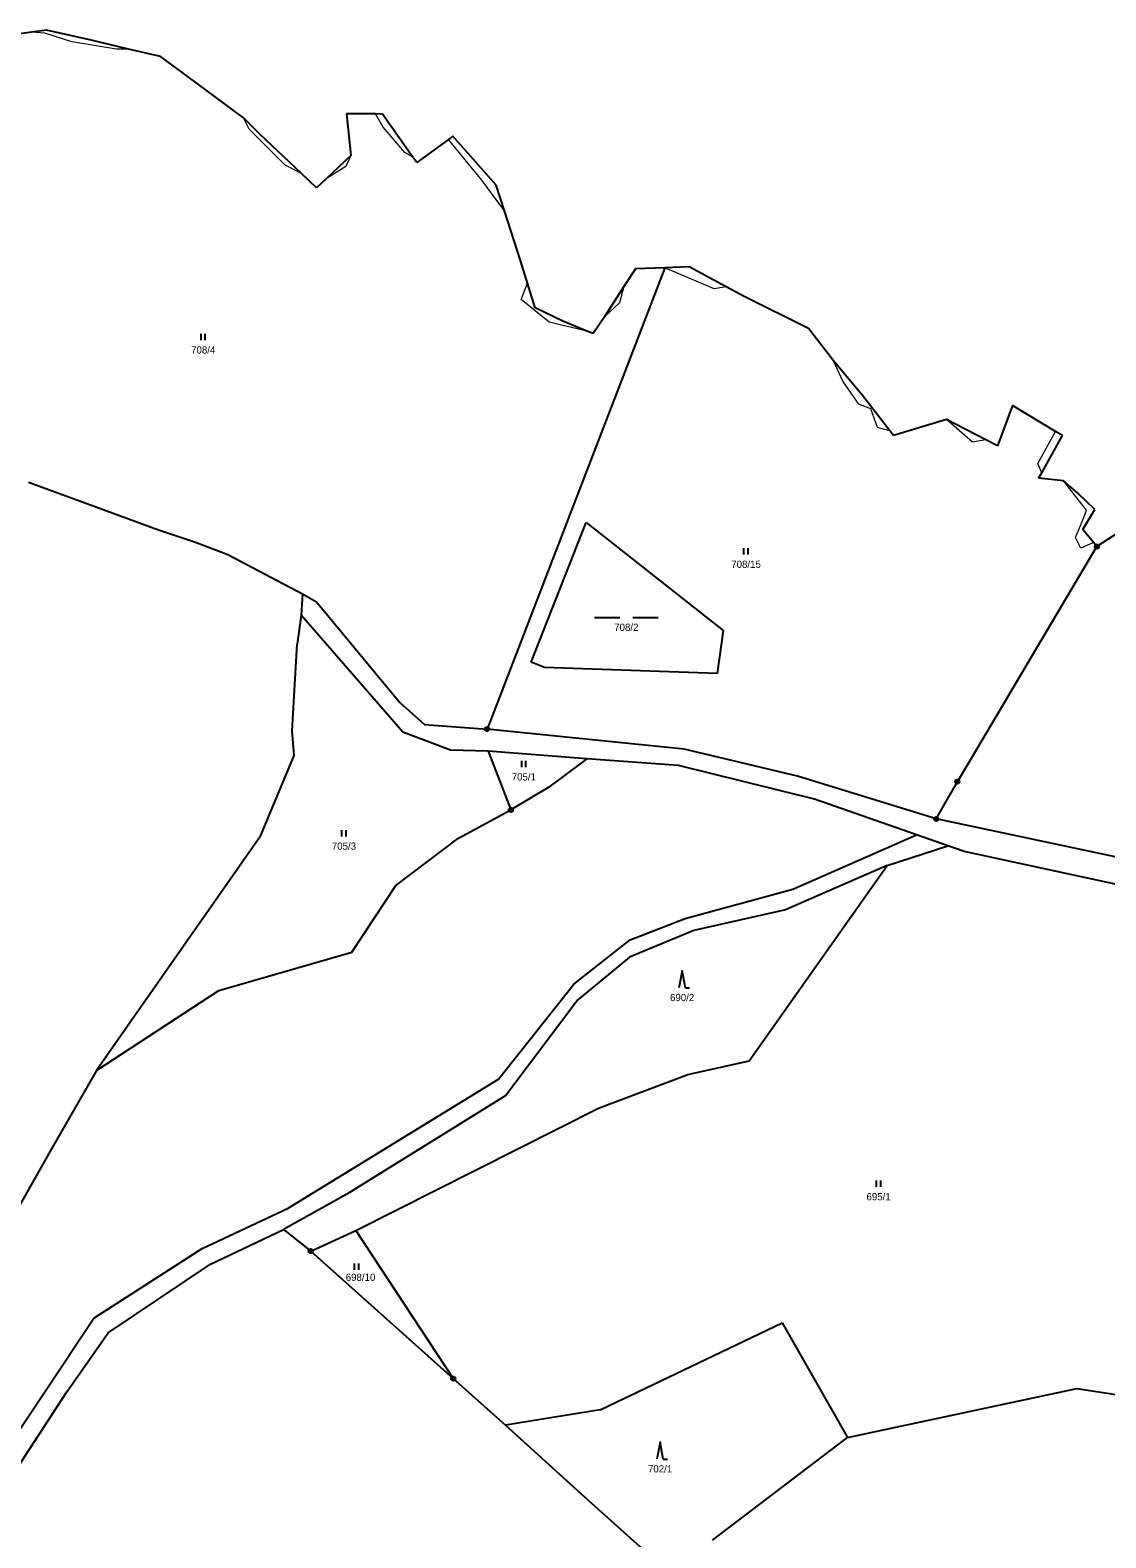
# Model space of a CAD drawing. Extents: x -739410 to -735662, y -942282 to -940043.
# Drawn here: x -738926.3 to -738673.5, y -941488.5 to -941134.3 of the extents above; entities that cross this region are included whole.
import ezdxf
from ezdxf.enums import TextEntityAlignment as Align

# ---------------------------------------------------------------- set-up
doc = ezdxf.new("R2010")
doc.units = 0
doc.header["$LTSCALE"] = 0.68
for name, color, linetype, lineweight in [('1', 7, 'Continuous', 25), ('3', 7, 'Continuous', 25), ('4', 7, 'Continuous', 13), ('8', 7, 'Continuous', 25)]:
    doc.layers.add(name, color=color, linetype=linetype, lineweight=lineweight)
doc.layers.add('2', color=7, linetype='Continuous')

msp = doc.modelspace()

# ---------------------------------------------------------------- linework, layer by layer
at = {"layer": '1'}
for p, q in [((-738925.92, -941134.78), (-738932.51, -941135.73)), ((-738922.47, -941134.29), (-738925.92, -941134.78)), ((-738911.93, -941136.68), (-738922.47, -941134.29)), ((-738903.14, -941138.74), (-738911.93, -941136.68)), ((-738895.68, -941140.49), (-738903.14, -941138.74)), ((-738889.13, -941145.22), (-738895.68, -941140.49)), ((-738876.12, -941154.87), (-738889.13, -941145.22)), ((-738872.28, -941158.73), (-738876.12, -941154.87)), ((-738851.94, -941153.93), (-738850.94, -941163.74)), ((-738845.13, -941153.98), (-738851.94, -941153.93)), ((-738843.49, -941153.99), (-738845.13, -941153.98)), ((-738836.41, -941164.03), (-738843.49, -941153.99)), ((-738862.51, -941168), (-738872.28, -941158.73)), ((-738826.94, -941159.23), (-738827.96, -941159.97)), ((-738816.76, -941170.68), (-738826.94, -941159.23)), ((-738827.96, -941159.97), (-738835.45, -941165.4)), ((-738850.94, -941163.74), (-738856.71, -941169.19)), ((-738835.45, -941165.4), (-738836.41, -941164.03)), ((-738858.99, -941171.34), (-738862.51, -941168)), ((-738856.71, -941169.19), (-738858.99, -941171.34)), ((-738814.81, -941176.75), (-738816.76, -941170.68)), ((-738811.06, -941188.39), (-738814.81, -941176.75)), ((-738777.17, -941190.11), (-738818.9, -941298.52)), ((-738809.41, -941193.73), (-738811.06, -941188.39)), ((-738784.06, -941190.39), (-738786.75, -941194.55)), ((-738777.17, -941190.11), (-738784.06, -941190.39)), ((-738771.44, -941189.89), (-738777.17, -941190.11)), ((-738762.72, -941194.6), (-738771.44, -941189.89)), ((-738807.6, -941199.56), (-738809.41, -941193.73)), ((-738786.75, -941194.55), (-738791.36, -941201.67)), ((-738758.51, -941196.87), (-738762.72, -941194.6)), ((-738743.38, -941204.38), (-738758.51, -941196.87)), ((-738801.11, -941202.63), (-738807.6, -941199.56)), ((-738791.36, -941201.67), (-738794.01, -941205.58)), ((-738795.46, -941204.98), (-738801.11, -941202.63)), ((-738794.01, -941205.58), (-738795.46, -941204.98)), ((-738724.25, -941228.42), (-738730.7, -941220.09)), ((-738695.48, -941222.44), (-738698.99, -941231.96)), ((-738685.36, -941228.57), (-738695.48, -941222.44)), ((-738710.94, -941225.77), (-738723.41, -941229.51)), ((-738701.71, -941230.55), (-738710.94, -941225.77)), ((-738723.41, -941229.51), (-738724.25, -941228.42)), ((-738698.99, -941231.96), (-738701.71, -941230.55)), ((-738688.61, -941238.29), (-738683.73, -941229.56)), ((-738683.73, -941229.56), (-738685.36, -941228.57)), ((-738926.63, -941240.49), (-738910.57, -941246.37)), ((-738689.32, -941239.56), (-738688.61, -941238.29)), ((-738683.49, -941240.16), (-738689.32, -941239.56)), ((-738680.13, -941243.05), (-738683.49, -941240.16)), ((-738676.09, -941246.88), (-738680.13, -941243.05)), ((-738910.57, -941246.37), (-738896.15, -941251.67)), ((-738678.98, -941251.65), (-738676.09, -941246.88)), ((-738896.15, -941251.67), (-738887.44, -941254.55)), ((-738808.55, -941282.75), (-738795.6, -941249.99)), ((-738795.6, -941249.99), (-738763.42, -941275.38)), ((-738676.44, -941254.66), (-738678.98, -941251.65)), ((-738665.06, -941248.73), (-738675.63, -941255.63)), ((-738887.44, -941254.55), (-738879.84, -941257.52)), ((-738675.63, -941255.63), (-738676.44, -941254.66)), ((-738879.84, -941257.52), (-738862.29, -941266.76)), ((-738708.42, -941310.86), (-738675.63, -941255.63)), ((-738862.29, -941266.76), (-738862.62, -941271.76)), ((-738862.29, -941266.76), (-738859, -941268.57)), ((-738859, -941268.57), (-738839.4, -941292.25)), ((-738862.62, -941271.76), (-738863.56, -941278.52)), ((-738838.71, -941299.26), (-738862.62, -941271.76)), ((-738763.42, -941275.38), (-738764.85, -941285.48)), ((-738864.75, -941298.95), (-738863.56, -941278.52)), ((-738805.39, -941284), (-738808.55, -941282.75)), ((-738764.85, -941285.48), (-738805.39, -941284)), ((-738839.4, -941292.25), (-738833.6, -941297.42)), ((-738833.6, -941297.42), (-738818.9, -941298.52)), ((-738864.26, -941304.72), (-738864.75, -941298.95)), ((-738827.49, -941303.43), (-738838.71, -941299.26)), ((-738772.6, -941303.2), (-738818.9, -941298.52)), ((-738872.13, -941323.67), (-738864.26, -941304.72)), ((-738818.68, -941303.66), (-738827.49, -941303.43)), ((-738818.68, -941303.66), (-738813.33, -941317.49)), ((-738795.51, -941305.47), (-738818.68, -941303.66)), ((-738745.97, -941309.54), (-738772.6, -941303.2)), ((-738795.51, -941305.47), (-738804.44, -941312.19)), ((-738773.94, -941307.05), (-738795.51, -941305.47)), ((-738741.99, -941314.94), (-738773.94, -941307.05)), ((-738804.44, -941312.19), (-738813.33, -941317.49)), ((-738713.4, -941319.63), (-738745.97, -941309.54)), ((-738713.4, -941319.63), (-738708.42, -941310.86)), ((-738718.04, -941323.34), (-738741.99, -941314.94)), ((-738825.6, -941324.14), (-738813.33, -941317.49)), ((-738668.73, -941329.06), (-738713.4, -941319.63)), ((-738872.13, -941323.67), (-738910.7, -941378.73)), ((-738840.34, -941335.26), (-738825.6, -941324.14)), ((-738747.11, -941336.1), (-738718.04, -941323.34)), ((-738724.92, -941330.59), (-738710.68, -941325.92)), ((-738710.68, -941325.92), (-738718.04, -941323.34)), ((-738706.8, -941327.28), (-738710.68, -941325.92)), ((-738669.84, -941335.26), (-738706.8, -941327.28)), ((-738757.36, -941376.45), (-738724.92, -941330.59)), ((-738724.92, -941330.59), (-738748.77, -941340.98)), ((-738850.68, -941350.9), (-738840.34, -941335.26)), ((-738772.36, -941343.03), (-738747.11, -941336.1)), ((-738785.31, -941348.03), (-738772.36, -941343.03)), ((-738748.77, -941340.98), (-738770.31, -941345.85)), ((-738770.31, -941345.85), (-738785.44, -941352.13)), ((-738881.95, -941359.95), (-738850.68, -941350.9)), ((-738798.52, -941358.42), (-738785.31, -941348.03)), ((-738785.44, -941352.13), (-738797.62, -941362.14)), ((-738910.7, -941378.73), (-738881.95, -941359.95)), ((-738816.21, -941380.73), (-738798.52, -941358.42)), ((-738797.62, -941362.14), (-738814.55, -941384.58)), ((-738910.7, -941378.73), (-738921.59, -941397.65)), ((-738771.72, -941379.66), (-738757.36, -941376.45)), ((-738865.62, -941411.03), (-738816.21, -941380.73)), ((-738792.71, -941387.61), (-738771.72, -941379.66)), ((-738814.55, -941384.58), (-738851.86, -941407.8)), ((-738849.77, -941416.34), (-738792.71, -941387.61)), ((-738921.59, -941397.65), (-738930.47, -941413.51)), ((-738851.86, -941407.8), (-738866.75, -941416.1)), ((-738885.88, -941420.52), (-738865.62, -941411.03)), ((-738883.87, -941424.26), (-738866.75, -941416.1)), ((-738866.75, -941416.1), (-738860.36, -941421.14)), ((-738860.36, -941421.14), (-738849.77, -941416.34)), ((-738849.77, -941416.34), (-738826.86, -941451.12)), ((-738911.35, -941436.94), (-738885.88, -941420.52)), ((-738860.36, -941421.14), (-738826.86, -941451.12)), ((-738907.92, -941440.32), (-738883.87, -941424.26)), ((-738942.74, -941483.93), (-738911.35, -941436.94)), ((-738792.34, -941458.43), (-738749.6, -941437.98)), ((-738749.6, -941437.98), (-738734.21, -941464.91)), ((-738917.62, -941454.18), (-738907.92, -941440.32)), ((-738826.86, -941451.12), (-738814.62, -941462.07)), ((-738734.21, -941464.91), (-738680.39, -941453.41)), ((-738680.39, -941453.41), (-738661.81, -941456.28)), ((-738928.6, -941471.03), (-738917.62, -941454.18)), ((-738792.34, -941458.43), (-738814.62, -941462.07)), ((-738814.62, -941462.07), (-738795.06, -941479.78)), ((-738765.92, -941489.07), (-738734.21, -941464.91)), ((-738795.06, -941479.78), (-738772.58, -941499.84))]:
    msp.add_line(p, q, dxfattribs=at)
msp.add_lwpolyline([(-738730.7, -941220.09), (-738737.52, -941211.97), (-738743.38, -941204.38)], dxfattribs=at)
at = {"layer": '3'}
for p, q in [((-738886.121, -941207.15), (-738886.121, -941205.65)), ((-738885.12, -941207.15), (-738885.12, -941205.65)), ((-738758.581, -941257.5), (-738758.581, -941256)), ((-738757.58, -941257.5), (-738757.58, -941256)), ((-738793.689, -941272.3), (-738787.689, -941272.3)), ((-738784.689, -941272.3), (-738778.689, -941272.3)), ((-738810.791, -941307.46), (-738810.791, -941305.96)), ((-738809.79, -941307.46), (-738809.79, -941305.96)), ((-738853.061, -941323.73), (-738853.061, -941322.23)), ((-738852.06, -941323.73), (-738852.06, -941322.23)), ((-738772.33, -941359.3), (-738771.334, -941359.3)), ((-738727.431, -941406.09), (-738727.431, -941404.59)), ((-738726.43, -941406.09), (-738726.43, -941404.59)), ((-738850.051, -941425.53), (-738850.051, -941424.03)), ((-738849.05, -941425.53), (-738849.05, -941424.03)), ((-738777.52, -941470.04), (-738776.524, -941470.04))]:
    msp.add_line(p, q, dxfattribs=at)
for points in [[(-738772.33, -941359.3), (-738773.08, -941355.3), (-738773.83, -941359.3)], [(-738777.52, -941470.04), (-738778.27, -941466.04), (-738779.02, -941470.04)]]:
    msp.add_lwpolyline(points, dxfattribs=at)
at = {"layer": '4'}
for p, q in [((-738922.8, -941135), (-738925.92, -941134.78)), ((-738916.47, -941137.02), (-738922.8, -941135)), ((-738905.98, -941138.77), (-738916.47, -941137.02)), ((-738903.14, -941138.74), (-738905.98, -941138.77)), ((-738874.83, -941157.55), (-738876.12, -941154.87)), ((-738843.31, -941157.06), (-738845.13, -941153.98)), ((-738866.39, -941166), (-738874.83, -941157.55)), ((-738838.22, -941163.06), (-738843.31, -941157.06)), ((-738836.41, -941164.03), (-738838.22, -941163.06)), ((-738820.18, -941169.51), (-738827.96, -941159.97)), ((-738862.51, -941168), (-738866.39, -941166)), ((-738852.14, -941166.3), (-738856.71, -941169.19)), ((-738850.94, -941163.74), (-738852.14, -941166.3)), ((-738814.81, -941176.75), (-738820.18, -941169.51)), ((-738765.55, -941195.09), (-738777.17, -941190.11)), ((-738810.9, -941197.6), (-738809.41, -941193.73)), ((-738786.75, -941194.55), (-738787.79, -941198.36)), ((-738762.72, -941194.6), (-738765.55, -941195.09)), ((-738804.36, -941202.88), (-738810.9, -941197.6)), ((-738787.79, -941198.36), (-738791.36, -941201.67)), ((-738795.46, -941204.98), (-738804.36, -941202.88)), ((-738735.3, -941216.73), (-738737.52, -941211.97)), ((-738731.58, -941222.19), (-738735.3, -941216.73)), ((-738728.79, -941223.25), (-738731.58, -941222.19)), ((-738727.19, -941227.64), (-738728.79, -941223.25)), ((-738704.86, -941231.09), (-738710.94, -941225.77)), ((-738724.25, -941228.42), (-738727.19, -941227.64)), ((-738701.71, -941230.55), (-738704.86, -941231.09)), ((-738689.51, -941236.09), (-738685.36, -941228.57)), ((-738688.61, -941238.29), (-738689.51, -941236.09)), ((-738678.07, -941247.06), (-738683.49, -941240.16)), ((-738678.74, -941248.79), (-738678.07, -941247.06)), ((-738680.67, -941253.51), (-738678.74, -941248.79)), ((-738679.4, -941255.97), (-738680.67, -941253.51)), ((-738676.44, -941254.66), (-738679.4, -941255.97))]:
    msp.add_line(p, q, dxfattribs=at)
at = {"layer": '8'}
for centre, radius in [((-738675.63, -941255.6299), 0.5), ((-738675.63, -941255.6299), 0.0303), ((-738818.9, -941298.5199), 0.5), ((-738818.9, -941298.5199), 0.0303), ((-738708.42, -941310.8599), 0.5), ((-738708.42, -941310.8599), 0.0303), ((-738813.33, -941317.4899), 0.5), ((-738813.33, -941317.4899), 0.0303), ((-738713.4, -941319.6299), 0.5), ((-738713.4, -941319.6299), 0.0303), ((-738860.36, -941421.1399), 0.5), ((-738860.36, -941421.1399), 0.0303), ((-738826.86, -941451.1199), 0.5), ((-738826.86, -941451.1199), 0.0303)]:
    msp.add_circle(centre, radius, dxfattribs=at)

# ---------------------------------------------------------------- texts
at = {"layer": '2'}
for s, p in [('708/4', (-738885.61, -941210.275)), ('708/15', (-738758.07, -941260.625)), ('708/2', (-738786.2, -941275.425)), ('705/1', (-738810.28, -941310.585)), ('705/3', (-738852.55, -941326.855)), ('690/2', (-738773.08, -941362.425)), ('695/1', (-738726.92, -941409.215)), ('698/10', (-738848.65, -941428.145)), ('702/1', (-738778.27, -941473.165))]:
    msp.add_text(s, height=1.7, dxfattribs=at).set_placement(p, align=Align.CENTER)

doc.saveas('drawing.dxf')
